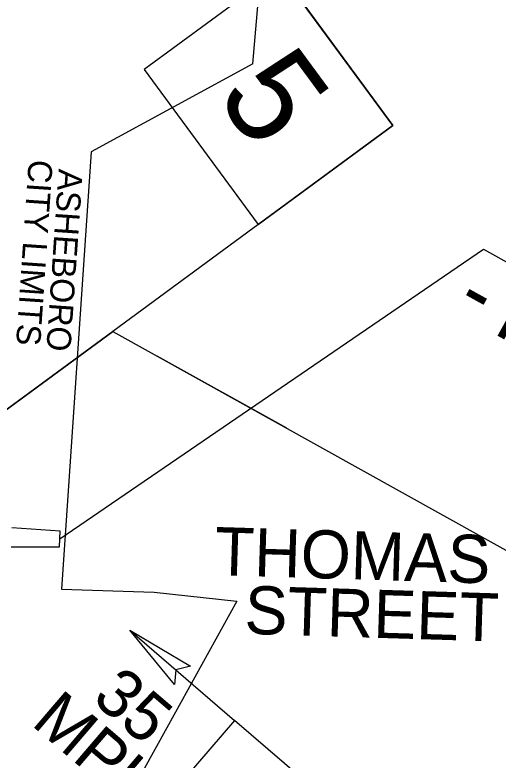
# Model space of a CAD drawing. Extents: x 1754939 to 1770240, y 706534 to 717510.
# Drawn here: x 1764273 to 1764774, y 711317 to 712091 of the extents above; entities that cross this region are included whole.
import ezdxf

# ---------------------------------------------------------------- set-up
doc = ezdxf.new("R2010")
doc.units = 0
for name, color, linetype in [('ENG SEALS CELL', 7, 'Continuous'), ('Old_Level_2', 7, 'Continuous'), ('Prop Guardrail Anchor Unit CELL', 7, 'Continuous'), ('Prop Lane Arrow CELL', 7, 'Continuous'), ('Prop SS Cut Line', 7, 'Continuous'), ('Sheet PE Seal Cell', 7, 'Continuous')]:
    doc.layers.add(name, color=color, linetype=linetype)

msp = doc.modelspace()

# ---------------------------------------------------------------- linework, layer by layer
at = {"layer": 'ENG SEALS CELL'}
msp.add_line((1764555, 711661.35), (1764420.35, 711736.33), dxfattribs=at)
for points in [[(1763819.2, 711353.8), (1763256.69, 712119.21), (1763567.05, 712347.56), (1763674.28, 712850.23), (1763900.75, 713016.09), (1764665.15, 711975.79), (1764374.33, 711761.96)], [(1764665.15, 711975.79), (1764546.68, 712136.98), (1764406.84, 712034.2), (1764525.31, 711873.01)], [(1763634.19, 710972.32), (1763634.19, 710972.32), (1763865.66, 711387.96), (1764374.33, 711761.96), (1765360.91, 711212.55), (1765258.03, 711027.8), (1764850.07, 710295.22)]]:
    msp.add_lwpolyline(points, close=True, dxfattribs=at)
at = {"layer": 'Old_Level_2'}
for p, q in [((1764391.98, 711451.8), (1764500.76, 711357.98)), ((1764500.76, 711357.98), (1764316.79, 711144.67)), ((1764616.39, 711258.25), (1764500.76, 711357.98))]:
    msp.add_line(p, q, dxfattribs=at)
at = {"layer": 'Prop Guardrail Anchor Unit CELL'}
msp.add_lwpolyline([(1764438.41, 711395.38), (1764391.98, 711451.8), (1764455.17, 711414.21), (1764439.84, 711410.52)], close=True, dxfattribs=at)
at = {"layer": 'Prop Lane Arrow CELL'}
for p, q in [((1764319.68, 711554.54), (1764269.77, 711558.12)), ((1764319.15, 711538.42), (1764319.68, 711554.54)), ((1764269.12, 711538.13), (1764319.15, 711538.42))]:
    msp.add_line(p, q, dxfattribs=at)
at = {"layer": 'Prop SS Cut Line'}
for p, q in [((1764319.42, 711546.5), (1764759.04, 711847.29)), ((1764759.04, 711847.29), (1765622.52, 711366.44))]:
    msp.add_line(p, q, dxfattribs=at)
at = {"layer": 'Sheet PE Seal Cell'}
for points in [[(1764519.91, 712039.92), (1764525.25, 712104.05), (1764402.51, 712099.99), (1764283.1, 712100.68), (1764279.41, 712139.2), (1764285.15, 712267.71), (1764286.41, 712288.54), (1764418.11, 712260.63)], [(1764519.91, 712039.92), (1764352.14, 711948.61), (1764321.17, 711494.28)], [(1764321.17, 711494.28), (1764417.37, 711491.32), (1764503.08, 711481.71), (1764430.33, 711350.08), (1764293.62, 711102.75)]]:
    msp.add_lwpolyline(points, dxfattribs=at)

# ---------------------------------------------------------------- texts
at = {"layer": 'ENG SEALS CELL'}
msp.add_text('5', height=100, rotation=306.31442, dxfattribs=at).set_placement((1764480.29, 712006.47))
at = {"layer": 'Old_Level_2'}
for s, p in [('35', (1764351.57, 711378.9)), ('MPH', (1764288.56, 711353.84))]:
    msp.add_text(s, height=50, rotation=319.47643, dxfattribs=at).set_placement(p)
at = {"layer": 'Prop SS Cut Line'}
msp.add_text('-Y5- POT Sta. 13+00.00', height=63.75, rotation=330.88754, dxfattribs=at).set_placement((1764727.48, 711783.24))
at = {"layer": 'Sheet PE Seal Cell'}
for s, height, rotation, p in [('CITY LIMITS', 25, 266.10072, (1764287.2, 711940.89)), ('ASHEBORO ', 25, 266.10072, (1764318.3, 711931.19)), ('THOMAS ', 50, 358.23666, (1764479.69, 711508.95)), ('STREET', 50, 358.23666, (1764510.58, 711447.97))]:
    msp.add_text(s, height=height, rotation=rotation, dxfattribs=at).set_placement(p)

doc.saveas('drawing.dxf')
